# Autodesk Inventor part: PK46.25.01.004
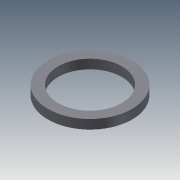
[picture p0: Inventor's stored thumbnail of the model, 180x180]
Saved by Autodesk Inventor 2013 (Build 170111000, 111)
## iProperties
Created: 2005-04
Part Number: PK46.25.01.004
Material: Steel, Mild
Document SubType Name: Modeling
Designer: salex
Manufacturer: Standard
Standards Organization: Custom
Density: 7.86 g/cm^3
Author: salex
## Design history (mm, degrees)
sketch "Эскиз1"
  geometry: C1 r 62.5 at (0, 0); C2 r 82.5 at (0, 0)
  constraints: 2 centre point, 1 coincident, 1 other
  dimensions: "d0" = 125 diameter of C1; "d1" = 165 diameter of C2
extrude "Выдавливание1" new body sketch "Эскиз1" distance "d2" = 18; taper "d3" = 0 deg
body "Solid1"
